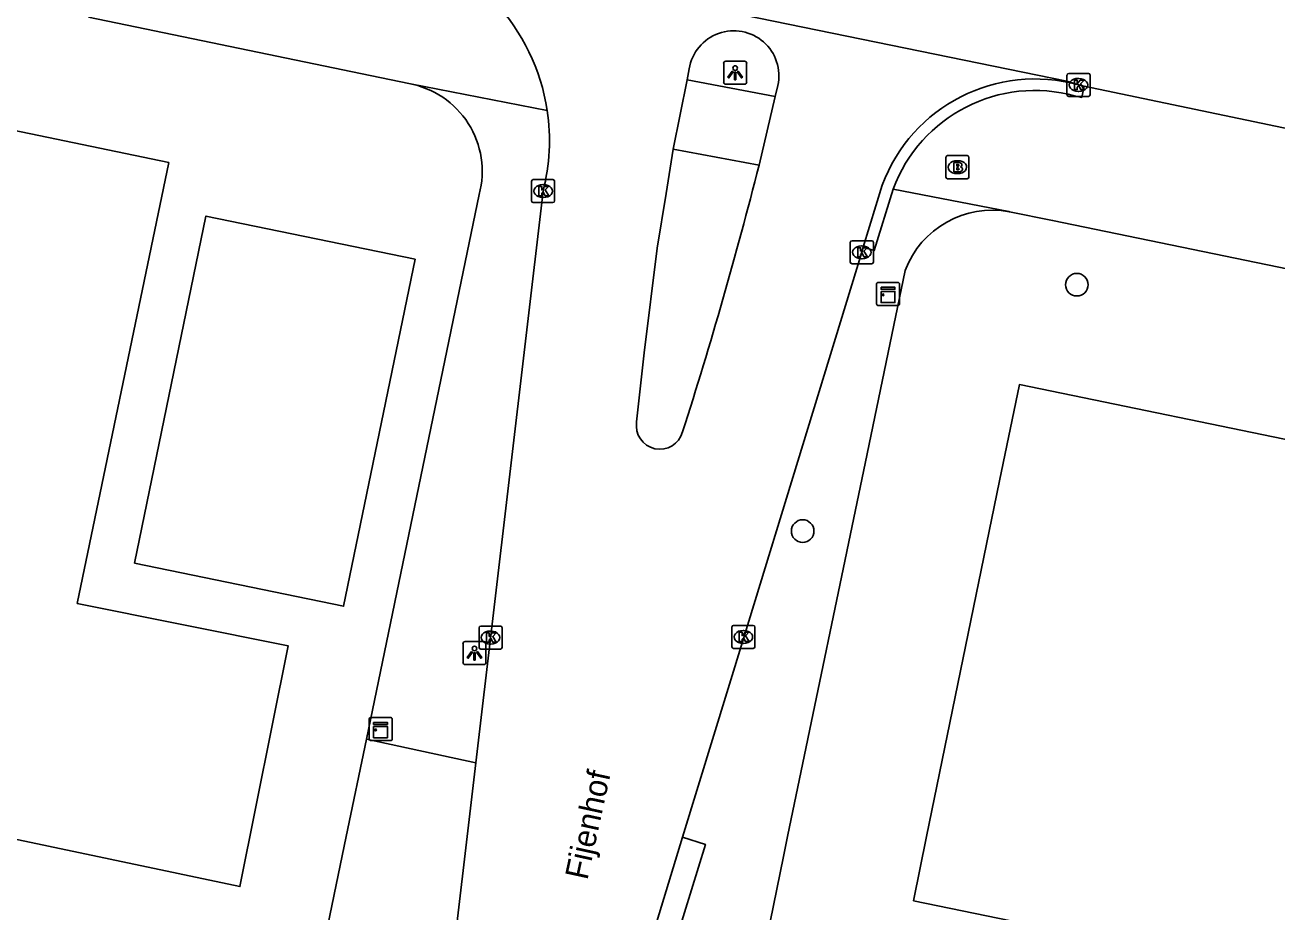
# Model space of a CAD drawing. Extents: x 157692 to 159670, y 381454 to 383289.
# Drawn here: x 158244.1 to 158298.4, y 382496.7 to 382535.2 of the extents above; entities that cross this region are included whole.
import ezdxf

# ---------------------------------------------------------------- set-up
doc = ezdxf.new("R2010")
doc.units = 0
for name, color, linetype in [('IMGEO_Boom', 7, 'Continuous'), ('IMGEO_Brandkraan', 7, 'Continuous'), ('IMGEO_Kast', 7, 'Continuous'), ('IMGEO_Kolk', 7, 'Continuous'), ('IMGEO_Lichtpunt', 7, 'Continuous'), ('IMGEO_Openbare_ruimte_label', 7, 'Continuous'), ('IMGEO_Pand', 7, 'Continuous'), ('IMGEO_Rijbaan_lokaal_gesloten', 7, 'Continuous'), ('IMGEO_Rijbaan_lokaal_open', 7, 'Continuous'), ('IMGEO_Voetpad_open', 7, 'Continuous')]:
    doc.layers.add(name, color=color, linetype=linetype)

msp = doc.modelspace()

# ---------------------------------------------------------------- linework, layer by layer
at = {"layer": 'IMGEO_Boom'}
for centre in [(158289.692, 382523.909), (158277.808, 382513.237)]:
    msp.add_circle(centre, 0.489, dxfattribs=at)
at = {"layer": 'IMGEO_Brandkraan'}
for p, q in [((158284.012, 382528.574), (158284.012, 382529.426)), ((158284.087, 382529.5), (158284.939, 382529.5)), ((158284.5, 382529.28), (158284.525, 382529.28)), ((158285.013, 382529.426), (158285.013, 382528.574)), ((158284.523, 382528.72), (158284.498, 382528.72)), ((158284.939, 382528.5), (158284.087, 382528.5))]:
    msp.add_line(p, q, dxfattribs=at)
for points in [[(158284.012, 382528.574), (158284.012, 382529.426)], [(158284.087, 382529.5), (158284.939, 382529.5)], [(158284.36, 382529.2), (158284.36, 382528.8), (158284.573, 382528.8)], [(158284.591, 382529.2), (158284.36, 382529.2)], [(158285.013, 382529.426), (158285.013, 382528.574)], [(158284.539, 382529.119), (158284.485, 382529.119), (158284.485, 382529.043)], [(158284.485, 382529.043), (158284.538, 382529.043)], [(158284.547, 382528.967), (158284.485, 382528.967), (158284.485, 382528.886)], [(158284.485, 382528.886), (158284.547, 382528.886)], [(158284.939, 382528.5), (158284.087, 382528.5)]]:
    msp.add_lwpolyline(points, dxfattribs=at)
for centre, radius, start, end in [((158284.089, 382529.424), 0.0765, 91.552, 178.448), ((158284.089, 382529.424), 0.0765, 91.552, 178.448), ((158284.595, 382529.055), 0.145, 59.4692, 91.5367), ((158284.62, 382529.102), 0.0922, 285.5137, 58.1501), ((158284.937, 382529.424), 0.0765, 1.552, 88.448), ((158284.937, 382529.424), 0.0765, 1.552, 88.448), ((158284.54, 382529.081), 0.0379, 267.8285, 90.9355), ((158284.548, 382528.926), 0.0404, 269.8759, 90.5077), ((158284.579, 382529.051), 0.251, 268.6676, 293.5347), ((158284.625, 382528.91), 0.105, 301.3115, 78.989), ((158284.089, 382528.576), 0.0765, 181.552, 268.448), ((158284.089, 382528.576), 0.0765, 181.552, 268.448), ((158284.937, 382528.576), 0.0765, 271.552, 358.448), ((158284.937, 382528.576), 0.0765, 271.552, 358.448)]:
    msp.add_arc(centre, radius, start, end, dxfattribs=at)
for centre, major_axis, ratio, start_param, end_param in [((158284.499, 382529), (-0.387, 0.002), 0.722429, 4.712389, 7.853982), ((158284.524, 382529), (-0.39, 0.002), 0.717154, 1.570796, 4.712389)]:
    msp.add_ellipse(centre, major_axis=major_axis, ratio=ratio, start_param=start_param, end_param=end_param, dxfattribs=at)
at = {"layer": 'IMGEO_Kast'}
for p, q in [((158281.009, 382523.081), (158281.009, 382523.922)), ((158281.009, 382523.922), (158281.009, 382523.081)), ((158281.084, 382524.006), (158281.925, 382524.006)), ((158281.925, 382524.006), (158281.084, 382524.006)), ((158282.009, 382523.931), (158282.009, 382523.09)), ((158282.009, 382523.09), (158282.009, 382523.931)), ((158281.934, 382523.006), (158281.093, 382523.006)), ((158281.093, 382523.006), (158281.934, 382523.006)), ((158259.017, 382504.234), (158259.017, 382505.075)), ((158259.017, 382505.075), (158259.017, 382504.234)), ((158259.092, 382505.159), (158259.933, 382505.159)), ((158259.933, 382505.159), (158259.092, 382505.159)), ((158260.017, 382505.084), (158260.017, 382504.243)), ((158260.017, 382504.243), (158260.017, 382505.084)), ((158259.942, 382504.159), (158259.101, 382504.159)), ((158259.101, 382504.159), (158259.942, 382504.159))]:
    msp.add_line(p, q, dxfattribs=at)
for points in [[(158281.204, 382523.796), (158281.804, 382523.796), (158281.804, 382523.711), (158281.204, 382523.711), (158281.204, 382523.796)], [(158281.204, 382523.621), (158281.804, 382523.621), (158281.804, 382523.132), (158281.204, 382523.132), (158281.204, 382523.621)], [(158259.212, 382504.949), (158259.812, 382504.949), (158259.812, 382504.864), (158259.212, 382504.864), (158259.212, 382504.949)], [(158259.212, 382504.774), (158259.812, 382504.774), (158259.812, 382504.285), (158259.212, 382504.285), (158259.212, 382504.774)]]:
    msp.add_lwpolyline(points, dxfattribs=at)
for centre in [(158281.288, 382523.47), (158259.296, 382504.623)]:
    msp.add_circle(centre, 0.0377, dxfattribs=at)
for centre, start, end in [((158281.087, 382523.928), 92.4484, 184.2845), ((158281.087, 382523.928), 92.4484, 184.2845), ((158281.931, 382523.928), 2.4484, 94.2845), ((158281.931, 382523.928), 2.4484, 94.2845), ((158281.087, 382523.084), 182.4484, 274.2845), ((158281.087, 382523.084), 182.4484, 274.2845), ((158281.931, 382523.084), 272.4484, 4.2845), ((158281.931, 382523.084), 272.4484, 4.2845), ((158259.095, 382505.081), 92.4484, 184.2845), ((158259.095, 382505.081), 92.4484, 184.2845), ((158259.939, 382505.081), 2.4484, 94.2845), ((158259.939, 382505.081), 2.4484, 94.2845), ((158259.095, 382504.237), 182.4484, 274.2845), ((158259.095, 382504.237), 182.4484, 274.2845), ((158259.939, 382504.237), 272.4484, 4.2845), ((158259.939, 382504.237), 272.4484, 4.2845)]:
    msp.add_arc(centre, 0.0779, start, end, dxfattribs=at)
at = {"layer": 'IMGEO_Kolk'}
for p, q in [((158289.264, 382532.138), (158289.264, 382532.99)), ((158289.339, 382533.064), (158290.191, 382533.064)), ((158290.265, 382532.99), (158290.265, 382532.138)), ((158289.752, 382532.844), (158289.777, 382532.844)), ((158290.191, 382532.064), (158289.339, 382532.064)), ((158289.775, 382532.284), (158289.75, 382532.284)), ((158266.057, 382527.539), (158266.057, 382528.391)), ((158266.132, 382528.465), (158266.984, 382528.465)), ((158266.545, 382528.245), (158266.57, 382528.245)), ((158267.058, 382528.391), (158267.058, 382527.539)), ((158266.568, 382527.685), (158266.543, 382527.685)), ((158266.984, 382527.465), (158266.132, 382527.465)), ((158279.872, 382524.887), (158279.872, 382525.739)), ((158279.947, 382525.813), (158280.799, 382525.813)), ((158280.36, 382525.593), (158280.385, 382525.593)), ((158280.873, 382525.739), (158280.873, 382524.887)), ((158280.799, 382524.813), (158279.947, 382524.813)), ((158280.383, 382525.033), (158280.358, 382525.033)), ((158263.855, 382509.123), (158264.707, 382509.123)), ((158274.738, 382508.224), (158274.738, 382509.076)), ((158274.813, 382509.15), (158275.665, 382509.15)), ((158275.739, 382509.076), (158275.739, 382508.224)), ((158263.78, 382508.197), (158263.78, 382509.049)), ((158264.268, 382508.903), (158264.293, 382508.903)), ((158264.781, 382509.049), (158264.781, 382508.197)), ((158275.226, 382508.93), (158275.251, 382508.93)), ((158264.707, 382508.123), (158263.855, 382508.123)), ((158264.291, 382508.343), (158264.266, 382508.343)), ((158275.665, 382508.15), (158274.813, 382508.15)), ((158275.249, 382508.37), (158275.224, 382508.37))]:
    msp.add_line(p, q, dxfattribs=at)
for points in [[(158289.264, 382532.138), (158289.264, 382532.99)], [(158289.339, 382533.064), (158290.191, 382533.064)], [(158290.265, 382532.99), (158290.265, 382532.138)], [(158289.585, 382532.764), (158289.708, 382532.764), (158289.708, 382532.613), (158289.838, 382532.764), (158290.002, 382532.764), (158289.856, 382532.613), (158290.009, 382532.364), (158289.857, 382532.364), (158289.772, 382532.528), (158289.708, 382532.461), (158289.708, 382532.364), (158289.585, 382532.364), (158289.585, 382532.764)], [(158290.191, 382532.064), (158289.339, 382532.064)], [(158266.057, 382527.539), (158266.057, 382528.391)], [(158266.132, 382528.465), (158266.984, 382528.465)], [(158266.378, 382528.165), (158266.501, 382528.165), (158266.501, 382528.014), (158266.631, 382528.165), (158266.795, 382528.165), (158266.649, 382528.014), (158266.802, 382527.765), (158266.65, 382527.765), (158266.565, 382527.929), (158266.501, 382527.862), (158266.501, 382527.765), (158266.378, 382527.765), (158266.378, 382528.165)], [(158267.058, 382528.391), (158267.058, 382527.539)], [(158266.984, 382527.465), (158266.132, 382527.465)], [(158279.872, 382524.887), (158279.872, 382525.739)], [(158279.947, 382525.813), (158280.799, 382525.813)], [(158280.193, 382525.513), (158280.316, 382525.513), (158280.316, 382525.362), (158280.446, 382525.513), (158280.61, 382525.513), (158280.464, 382525.362), (158280.617, 382525.113), (158280.465, 382525.113), (158280.38, 382525.277), (158280.316, 382525.21), (158280.316, 382525.113), (158280.193, 382525.113), (158280.193, 382525.513)], [(158280.873, 382525.739), (158280.873, 382524.887)], [(158280.799, 382524.813), (158279.947, 382524.813)], [(158263.855, 382509.123), (158264.707, 382509.123)], [(158274.738, 382508.224), (158274.738, 382509.076)], [(158274.813, 382509.15), (158275.665, 382509.15)], [(158275.739, 382509.076), (158275.739, 382508.224)], [(158263.78, 382508.197), (158263.78, 382509.049)], [(158264.101, 382508.823), (158264.224, 382508.823), (158264.224, 382508.672), (158264.354, 382508.823), (158264.518, 382508.823), (158264.372, 382508.672), (158264.525, 382508.423), (158264.373, 382508.423), (158264.288, 382508.587), (158264.224, 382508.52), (158264.224, 382508.423), (158264.101, 382508.423), (158264.101, 382508.823)], [(158264.781, 382509.049), (158264.781, 382508.197)], [(158275.059, 382508.85), (158275.182, 382508.85), (158275.182, 382508.699), (158275.312, 382508.85), (158275.476, 382508.85), (158275.33, 382508.699), (158275.483, 382508.45), (158275.331, 382508.45), (158275.246, 382508.614), (158275.182, 382508.547), (158275.182, 382508.45), (158275.059, 382508.45), (158275.059, 382508.85)], [(158264.707, 382508.123), (158263.855, 382508.123)], [(158275.665, 382508.15), (158274.813, 382508.15)]]:
    msp.add_lwpolyline(points, dxfattribs=at)
for centre, start, end in [((158289.341, 382532.988), 91.552, 178.448), ((158289.341, 382532.988), 91.552, 178.448), ((158290.189, 382532.988), 1.552, 88.448), ((158290.189, 382532.988), 1.552, 88.448), ((158289.341, 382532.14), 181.552, 268.448), ((158289.341, 382532.14), 181.552, 268.448), ((158290.189, 382532.14), 271.552, 358.448), ((158290.189, 382532.14), 271.552, 358.448), ((158266.134, 382528.389), 91.552, 178.448), ((158266.134, 382528.389), 91.552, 178.448), ((158266.982, 382528.389), 1.552, 88.448), ((158266.982, 382528.389), 1.552, 88.448), ((158266.134, 382527.541), 181.552, 268.448), ((158266.134, 382527.541), 181.552, 268.448), ((158266.982, 382527.541), 271.552, 358.448), ((158266.982, 382527.541), 271.552, 358.448), ((158279.949, 382525.737), 91.552, 178.448), ((158279.949, 382525.737), 91.552, 178.448), ((158280.797, 382525.737), 1.552, 88.448), ((158280.797, 382525.737), 1.552, 88.448), ((158279.949, 382524.889), 181.552, 268.448), ((158279.949, 382524.889), 181.552, 268.448), ((158280.797, 382524.889), 271.552, 358.448), ((158280.797, 382524.889), 271.552, 358.448), ((158263.857, 382509.047), 91.552, 178.448), ((158263.857, 382509.047), 91.552, 178.448), ((158264.705, 382509.047), 1.552, 88.448), ((158264.705, 382509.047), 1.552, 88.448), ((158274.815, 382509.074), 91.552, 178.448), ((158274.815, 382509.074), 91.552, 178.448), ((158275.663, 382509.074), 1.552, 88.448), ((158275.663, 382509.074), 1.552, 88.448), ((158263.857, 382508.199), 181.552, 268.448), ((158263.857, 382508.199), 181.552, 268.448), ((158264.705, 382508.199), 271.552, 358.448), ((158264.705, 382508.199), 271.552, 358.448), ((158274.815, 382508.226), 181.552, 268.448), ((158274.815, 382508.226), 181.552, 268.448), ((158275.663, 382508.226), 271.552, 358.448), ((158275.663, 382508.226), 271.552, 358.448)]:
    msp.add_arc(centre, 0.0765, start, end, dxfattribs=at)
for centre, major_axis, ratio, start_param, end_param in [((158289.751, 382532.564), (-0.387, 0.002), 0.722429, 4.712389, 7.853982), ((158289.776, 382532.564), (-0.39, 0.002), 0.717154, 1.570796, 4.712389), ((158266.544, 382527.965), (-0.387, 0.002), 0.722429, 4.712389, 7.853982), ((158266.569, 382527.965), (-0.39, 0.002), 0.717154, 1.570796, 4.712389), ((158280.359, 382525.313), (-0.387, 0.002), 0.722429, 4.712389, 7.853982), ((158280.384, 382525.313), (-0.39, 0.002), 0.717154, 1.570796, 4.712389), ((158264.267, 382508.623), (-0.387, 0.002), 0.722429, 4.712389, 7.853982), ((158264.292, 382508.623), (-0.39, 0.002), 0.717154, 1.570796, 4.712389), ((158275.225, 382508.65), (-0.387, 0.002), 0.722429, 4.712389, 7.853982), ((158275.25, 382508.65), (-0.39, 0.002), 0.717154, 1.570796, 4.712389)]:
    msp.add_ellipse(centre, major_axis=major_axis, ratio=ratio, start_param=start_param, end_param=end_param, dxfattribs=at)
at = {"layer": 'IMGEO_Lichtpunt'}
for p, q in [((158274.384, 382533.494), (158274.384, 382532.687)), ((158274.384, 382533.494), (158274.384, 382532.687)), ((158275.286, 382533.589), (158274.478, 382533.589)), ((158275.286, 382533.589), (158274.478, 382533.589)), ((158275.38, 382532.687), (158275.38, 382533.494)), ((158275.38, 382532.687), (158275.38, 382533.494)), ((158274.478, 382532.593), (158275.286, 382532.593)), ((158274.478, 382532.593), (158275.286, 382532.593)), ((158263.086, 382508.352), (158263.086, 382507.545)), ((158263.086, 382508.352), (158263.086, 382507.545)), ((158263.988, 382508.447), (158263.18, 382508.447)), ((158263.988, 382508.447), (158263.18, 382508.447)), ((158264.082, 382507.545), (158264.082, 382508.352)), ((158264.082, 382507.545), (158264.082, 382508.352)), ((158263.18, 382507.451), (158263.988, 382507.451)), ((158263.18, 382507.451), (158263.988, 382507.451))]:
    msp.add_line(p, q, dxfattribs=at)
for points in [[(158274.758, 382533.158), (158274.797, 382533.13), (158274.609, 382532.868), (158274.571, 382532.895), (158274.758, 382533.158)], [(158274.86, 382533.11), (158274.907, 382533.11), (158274.907, 382532.788), (158274.86, 382532.788), (158274.86, 382533.11)], [(158274.97, 382533.13), (158275.008, 382533.157), (158275.195, 382532.895), (158275.156, 382532.867), (158274.97, 382533.13)], [(158263.46, 382508.016), (158263.499, 382507.988), (158263.311, 382507.726), (158263.273, 382507.753), (158263.46, 382508.016)], [(158263.672, 382507.988), (158263.71, 382508.015), (158263.897, 382507.753), (158263.858, 382507.725), (158263.672, 382507.988)], [(158263.562, 382507.968), (158263.609, 382507.968), (158263.609, 382507.646), (158263.562, 382507.646), (158263.562, 382507.968)]]:
    msp.add_lwpolyline(points, dxfattribs=at)
for centre in [(158274.883, 382533.292), (158263.585, 382508.15)]:
    msp.add_circle(centre, 0.0994, dxfattribs=at)
for centre, start, end in [((158274.478, 382533.494), 90, 180), ((158274.478, 382533.494), 90, 180), ((158275.286, 382533.494), 0, 90), ((158275.286, 382533.494), 0, 90), ((158274.478, 382532.687), 180, 270), ((158274.478, 382532.687), 180, 270), ((158275.286, 382532.687), 270, 0), ((158275.286, 382532.687), 270, 360), ((158263.18, 382508.352), 90, 180), ((158263.18, 382508.352), 90, 180), ((158263.988, 382508.352), 0, 90), ((158263.988, 382508.352), 0, 90), ((158263.18, 382507.545), 180, 270), ((158263.18, 382507.545), 180, 270), ((158263.988, 382507.545), 270, 0), ((158263.988, 382507.545), 270, 360)]:
    msp.add_arc(centre, 0.0946, start, end, dxfattribs=at)
at = {"layer": 'IMGEO_Pand'}
for points in [[(158250.336, 382529.206), (158209.425, 382537.711), (158203.372, 382508.378), (158253.417, 382497.836), (158255.513, 382508.258), (158246.364, 382510.099), (158250.336, 382529.206)], [(158248.846, 382511.851), (158251.945, 382526.883), (158261.01, 382525.014), (158257.91, 382509.982), (158248.846, 382511.851)], [(158282.608, 382497.216), (158283.179, 382500), (158286.343, 382515.416), (158287.199, 382519.584), (158327.119, 382511.361), (158327.717, 382514.268), (158331.148, 382513.575), (158330.573, 382510.691), (158336.933, 382509.322), (158335.04, 382500), (158332.399, 382486.997), (158282.608, 382497.216)]]:
    msp.add_lwpolyline(points, dxfattribs=at)
at = {"layer": 'IMGEO_Rijbaan_lokaal_gesloten'}
for points in [[(158259.953, 382538.72), (158260.015, 382538.714), (158289.255, 382532.72), (158289.761, 382532.565)], [(158272.892, 382533.267), (158272.8, 382532.78)], [(158272.8, 382532.78), (158272.193, 382529.777)], [(158276.621, 382532.057), (158276.732, 382532.538)], [(158289.761, 382532.565), (158290.003, 382532.509)], [(158290.003, 382532.509), (158300.233, 382530.369)], [(158275.919, 382529.091), (158276.621, 382532.057)], [(158272.193, 382529.777), (158271.885, 382527.865), (158271.502, 382525.489), (158270.933, 382520.956), (158270.611, 382517.962)], [(158281.256, 382528.216), (158280.433, 382525.535)], [(158266.555, 382527.965), (158263.638, 382503.203)], [(158280.433, 382525.535), (158280.368, 382525.313), (158275.251, 382508.628), (158272.601, 382499.974)], [(158261.353, 382488.699), (158261.878, 382491.18), (158262.145, 382492.292), (158262.477, 382494.087), (158262.815, 382496.212), (158263.261, 382500), (158263.638, 382503.203)], [(158272.601, 382499.974), (158271.383, 382495.998)]]:
    msp.add_lwpolyline(points, dxfattribs=at)
for centre, radius, start, end in [((158258.058, 382530.152), 8.775, 8.558, 77.527), ((158274.822, 382532.955), 1.955, 347.6744, 170.827), ((158287.874, 382525.764), 7.058, 74.4945, 159.671), ((158258.069, 382530.153), 8.764, 345.5397, 8.5604), ((158080.202, 382578.966), 201.972, 342.29069, 345.70336), ((158271.619, 382517.803), 1.021, 171.0252, 344.4476)]:
    msp.add_arc(centre, radius, start, end, dxfattribs=at)
at = {"layer": 'IMGEO_Rijbaan_lokaal_open'}
for points in [[(158255.912, 382489.808), (158258.024, 382500), (158258.9, 382504.228)], [(158263.638, 382503.203), (158258.9, 382504.228)]]:
    msp.add_lwpolyline(points, dxfattribs=at)
at = {"layer": 'IMGEO_Voetpad_open'}
for points in [[(158260.737, 382532.625), (158246.852, 382535.497)], [(158260.737, 382532.625), (158260.805, 382532.616), (158266.735, 382531.458)], [(158272.8, 382532.78), (158276.621, 382532.057)], [(158290.003, 382532.509), (158289.905, 382532.024), (158289.627, 382532.083)], [(158275.919, 382529.091), (158272.193, 382529.777)], [(158258.9, 382504.228), (158263.789, 382527.821)], [(158281.725, 382528.042), (158280.913, 382525.384), (158280.433, 382525.535)], [(158281.725, 382528.042), (158286.738, 382527.074), (158286.766, 382527.066)], [(158360.284, 382511.928), (158352.753, 382513.48), (158347.768, 382514.508), (158288.641, 382526.697), (158286.766, 382527.066)], [(158282.251, 382524.529), (158280.6, 382516.583), (158277.155, 382500), (158276.977, 382499.143), (158273.828, 382483.723), (158266.997, 382450.348), (158258.469, 382408.937), (158257.074, 382402.077), (158248.209, 382358.844), (158244.45, 382340.754)], [(158272.601, 382499.974), (158273.594, 382499.664), (158272.388, 382495.735)]]:
    msp.add_lwpolyline(points, dxfattribs=at)
for centre, radius, start, end in [((158260.046, 382528.815), 3.872, 345.1303, 79.7256), ((158287.873, 382525.766), 6.556, 74.4809, 159.6886), ((158286.03, 382523.09), 4.044, 79.5158, 159.1479)]:
    msp.add_arc(centre, radius, start, end, dxfattribs=at)

# ---------------------------------------------------------------- texts
at = {"layer": 'IMGEO_Openbare_ruimte_label'}
msp.add_text('Fijenhof', height=1, rotation=77.7011, dxfattribs=at).set_placement((158268.475, 382498.085))

doc.saveas('drawing.dxf')
